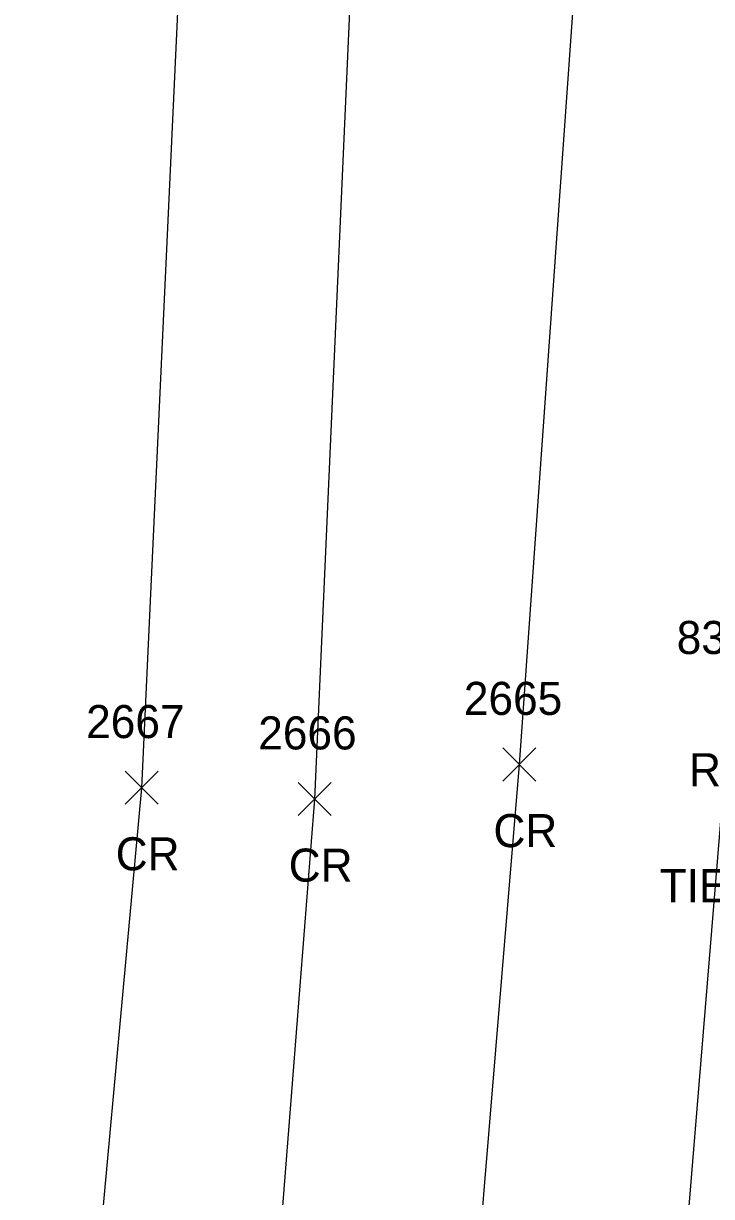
# Model space of a CAD drawing. Extents: x 1462089 to 1464015, y 730534 to 736144.
# Drawn here: x 1463197.8 to 1463239.4, y 733707.4 to 733778.4 of the extents above; entities that cross this region are included whole.
import ezdxf

# ---------------------------------------------------------------- set-up
doc = ezdxf.new("R2010")
doc.units = 0
for name, color, linetype in [('C_C', 7, 'Continuous'), ('P_A', 7, 'Continuous'), ('P_I', 7, 'Continuous'), ('P_TIC', 7, 'Continuous'), ('PET', 7, 'Continuous'), ('PRC', 7, 'Continuous')]:
    doc.layers.add(name, color=color, linetype=linetype)

msp = doc.modelspace()

# ---------------------------------------------------------------- linework, layer by layer
at = {"layer": 'P_TIC'}
for points in [[(1463226.746, 733732.581), (1463228.746, 733734.581)], [(1463228.746, 733732.581), (1463226.746, 733734.581)], [(1463203.898, 733731.178), (1463205.898, 733733.178)], [(1463205.898, 733731.178), (1463203.898, 733733.178)], [(1463214.363, 733730.492), (1463216.363, 733732.492)], [(1463216.363, 733730.492), (1463214.363, 733732.492)]]:
    msp.add_lwpolyline(points, dxfattribs=at)
at = {"layer": 'PET'}
msp.add_lwpolyline([(1463204.037, 733400.899), (1463213.278, 733462.856), (1463219.212, 733507.824), (1463223.327, 733545.685), (1463227.578, 733585.558), (1463231.524, 733632.81), (1463236.226, 733685.036), (1463240.526, 733737.266), (1463243.877, 733794.366), (1463244.491, 733836.173), (1463246.128, 733881.629), (1463247.529, 733928.635), (1463248.804, 733967.103), (1463249.861, 734010.387)], dxfattribs=at)
at = {"layer": 'PRC'}
for points in [[(1463215.188, 734017.403), (1463213.246, 733964.17), (1463212.713, 733918.287), (1463210.504, 733869.485), (1463210.318, 733836.277), (1463207.426, 733786.95), (1463204.898, 733732.178), (1463201.281, 733692.844), (1463197.145, 733640.94), (1463189.481, 733561.096), (1463184.103, 733515.992), (1463179.263, 733478.056), (1463173.047, 733431.971), (1463166.537, 733387.928)], [(1463226.225, 734016.91), (1463224.484, 733963.112), (1463223.017, 733916.36), (1463220.632, 733868.877), (1463220.757, 733836.132), (1463217.813, 733786.901), (1463215.363, 733731.492), (1463212.256, 733691.951), (1463207.891, 733639.469), (1463200.953, 733560.156), (1463195.256, 733512.527), (1463190.257, 733475.819), (1463184.256, 733428.992), (1463177.497, 733386.208)], [(1463237.77, 734016.397), (1463235.711, 733961.604), (1463234.889, 733915.525), (1463233.211, 733867.853), (1463232.126, 733835.029), (1463231.399, 733785.333), (1463227.746, 733733.581), (1463224.142, 733690.297), (1463219.974, 733638.182), (1463211.858, 733560.323), (1463206.748, 733509.815), (1463201.849, 733474.253), (1463195.707, 733430.165), (1463188.537, 733383.461)]]:
    msp.add_lwpolyline(points, dxfattribs=at)

# ---------------------------------------------------------------- texts
at = {"layer": 'C_C'}
msp.add_text('TIE=73.66 CENTER BOLT', height=2, dxfattribs=at).set_placement((1463236.238, 733725.251))
at = {"layer": 'P_A'}
for s, p in [('RDP', (1463238.014, 733732.266)), ('CR', (1463226.179, 733728.581)), ('CR', (1463203.331, 733727.178)), ('CR', (1463213.796, 733726.492))]:
    msp.add_text(s, height=2, dxfattribs=at).set_placement(p)
at = {"layer": 'P_I'}
for s, p in [('8373', (1463237.266, 733740.266)), ('2665', (1463224.391, 733736.581)), ('2667', (1463201.543, 733735.178)), ('2666', (1463211.954, 733734.492))]:
    msp.add_text(s, height=2, dxfattribs=at).set_placement(p)

doc.saveas('drawing.dxf')
